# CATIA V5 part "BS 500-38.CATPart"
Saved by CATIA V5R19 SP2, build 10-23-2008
Part number: BS 500-38
Bounding box of the stored display mesh (mm): x -18.951 to 18.951, y -18.952 to 18.952, z 0 to 106
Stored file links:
  C:\Users\Bora\Desktop\3D Katı model\BS serisi\BS 500\BS 500-38.CATPart
  C:\Program Files\Dassault Systemes\B19\intel_a\reffiles\standard\MetricThickPitch.txt
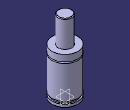
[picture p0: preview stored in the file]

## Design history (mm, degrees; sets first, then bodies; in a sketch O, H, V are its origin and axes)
Body1 (main body)
  Sketch1 on yz-plane, origin (0, 0, 0), H (0, 1, 0), V (0, 0, 1)
    point P1 (10, 105)
    point P3 (10, 105)
    point P5 (19, 57.5)
    point P6 (19, 55.5)
    point P9 (19, 57.5)
    point P14 (19, 55.5)
    line L1 (10, 105) -> (10, 67)
    arc A1 centre (9, 105) radius 1 from (10, 105) to (9, 106) ccw
    arc A2 centre (19, 56.5) radius 1 from (19, 57.5) to (19, 55.5) ccw
    line L2 (19, 0) -> (19, 4)
    line L3 (19, 57.5) -> (19, 67)
    line L4 (17, 7.5) -> (17, 4)
    line L5 (19, 7.5) -> (19, 55.5)
    line L6 (9, 106) -> (0, 106)
    point P15 (0, 106)
    line L7 (10, 67) -> (19, 67)
    line L8 (0, 0) -> (19, 0)
    line L9 (17, 7.5) -> (19, 7.5)
    line L10 (17, 4) -> (19, 4)
    coincidence: P15 V, P1 P3, P5 P9, P6 P14
    tangency: L6 A1
    horizontal: L7 H, L8 H, L9 H, L10 H
  Shaft1: profile Sketch1, axis Sketch1.V, angle 360
  Sketch2 on face of Shaft1 from Sketch1.L8, origin (0, 0, 0), H (1, 0, 0), V (0, -1, 0)
    point P1 (0, 0)
  Hole1: placed by Sketch2, at (0, 0, 0) direction (0, 0, 1), diameter 6.647, depth 4, threaded "M8", thread diameter 8, thread depth 4, pitch 1.25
